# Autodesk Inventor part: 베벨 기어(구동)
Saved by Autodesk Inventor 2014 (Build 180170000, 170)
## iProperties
Created: 2026-05
Part Number: 베벨 기어(구동)
Material: 일반
Document SubType Name: Modeling
Designer: dg
Density: 1 g/cm^3
Appearance: 기본값
Author: dg
Author: jhkim
Creation Date: 2026-04-23
Sending System: Autodesk Inventor 2027
Preprocessor: ST-DEVELOPER v20.1
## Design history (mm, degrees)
node "베벨 기어(구동)1"
body "Solid1"
node "기준1"
